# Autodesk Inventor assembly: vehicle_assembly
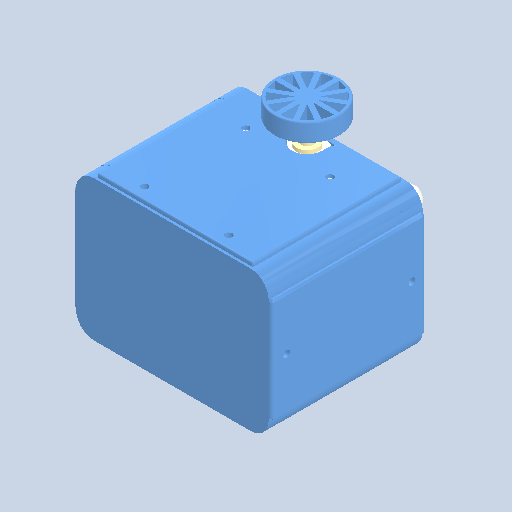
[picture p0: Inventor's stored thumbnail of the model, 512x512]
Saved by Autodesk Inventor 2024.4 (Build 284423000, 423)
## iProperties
Created: 2025-07
Part Number: vehicle_assembly
Document SubType Name: Assembly
Designer: AdminForWorker
Title: vehicle_assembly v2
Author: AdminForWorker
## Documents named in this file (15)
- c:\worker\convert-fusion-r03-cosv3\tmp\job-1\5\temp\files\c2717cec-cd30-4e2b-a2e5-52afbc4802da\639874b3-8927-4ec0-91ee-fd5e06a8bb76.iam
- c:\worker\convert-fusion-r03-cosv3\tmp\job-1\5\temp\files\c2717cec-cd30-4e2b-a2e5-52afbc4802da\roof v2.ipt
- c:\worker\convert-fusion-r03-cosv3\tmp\job-1\5\temp\files\c2717cec-cd30-4e2b-a2e5-52afbc4802da\pannel v2.ipt
- c:\worker\convert-fusion-r03-cosv3\tmp\job-1\5\temp\files\c2717cec-cd30-4e2b-a2e5-52afbc4802da\new_concept_floor v3.iam
- c:\worker\convert-fusion-r03-cosv3\tmp\job-1\5\temp\files\c2717cec-cd30-4e2b-a2e5-52afbc4802da\stepper_motor v3.ipt
- c:\worker\convert-fusion-r03-cosv3\tmp\job-1\5\temp\files\c2717cec-cd30-4e2b-a2e5-52afbc4802da\wheel_27 v1.ipt
- c:\worker\convert-fusion-r03-cosv3\tmp\job-1\5\temp\files\c2717cec-cd30-4e2b-a2e5-52afbc4802da\side_pannel v2.ipt
- c:\worker\convert-fusion-r03-cosv3\tmp\job-1\5\temp\files\c2717cec-cd30-4e2b-a2e5-52afbc4802da\support_insert v1.ipt
- c:\worker\convert-fusion-r03-cosv3\tmp\job-1\5\temp\files\c2717cec-cd30-4e2b-a2e5-52afbc4802da\support v1.iam
- c:\worker\convert-fusion-r03-cosv3\tmp\job-1\5\temp\files\c2717cec-cd30-4e2b-a2e5-52afbc4802da\support v1_1.iam
- c:\worker\convert-fusion-r03-cosv3\tmp\job-1\5\temp\files\c2717cec-cd30-4e2b-a2e5-52afbc4802da\support v1_2.iam
- c:\worker\convert-fusion-r03-cosv3\tmp\job-1\5\temp\files\c2717cec-cd30-4e2b-a2e5-52afbc4802da\support v1_3.iam
- c:\worker\convert-fusion-r03-cosv3\tmp\job-1\5\temp\files\c2717cec-cd30-4e2b-a2e5-52afbc4802da\pico v1.ipt
- c:\worker\convert-fusion-r03-cosv3\tmp\job-1\5\temp\files\c2717cec-cd30-4e2b-a2e5-52afbc4802da\stepper_motor_controller v2.ipt
- c:\worker\convert-fusion-r03-cosv3\tmp\job-1\5\temp\files\c2717cec-cd30-4e2b-a2e5-52afbc4802da\battery_pack v2.ipt
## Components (22 placed, 11 different names)
1. roof v2:1
2. pannel v2:1
3. new_concept_floor v3:1 [sub-assembly]
4. pannel v2:2
5. stepper_motor v3:1
6. stepper_motor v3:2
7. wheel_27 v1:1
8. wheel_27 v1:2
9. side_pannel v2:1
10. side_pannel v2:2
11. support_insert v1:1
12. support_insert v1:2
13. support_insert v1:3
14. support_insert v1:4
15. support v1:1 [sub-assembly]
16. support v1:2 [sub-assembly]
17. support v1:3 [sub-assembly]
18. support v1:4 [sub-assembly]
19. pico v1:1
20. stepper_motor_controller v2:1
21. stepper_motor_controller v2:2
22. battery_pack v2:1
